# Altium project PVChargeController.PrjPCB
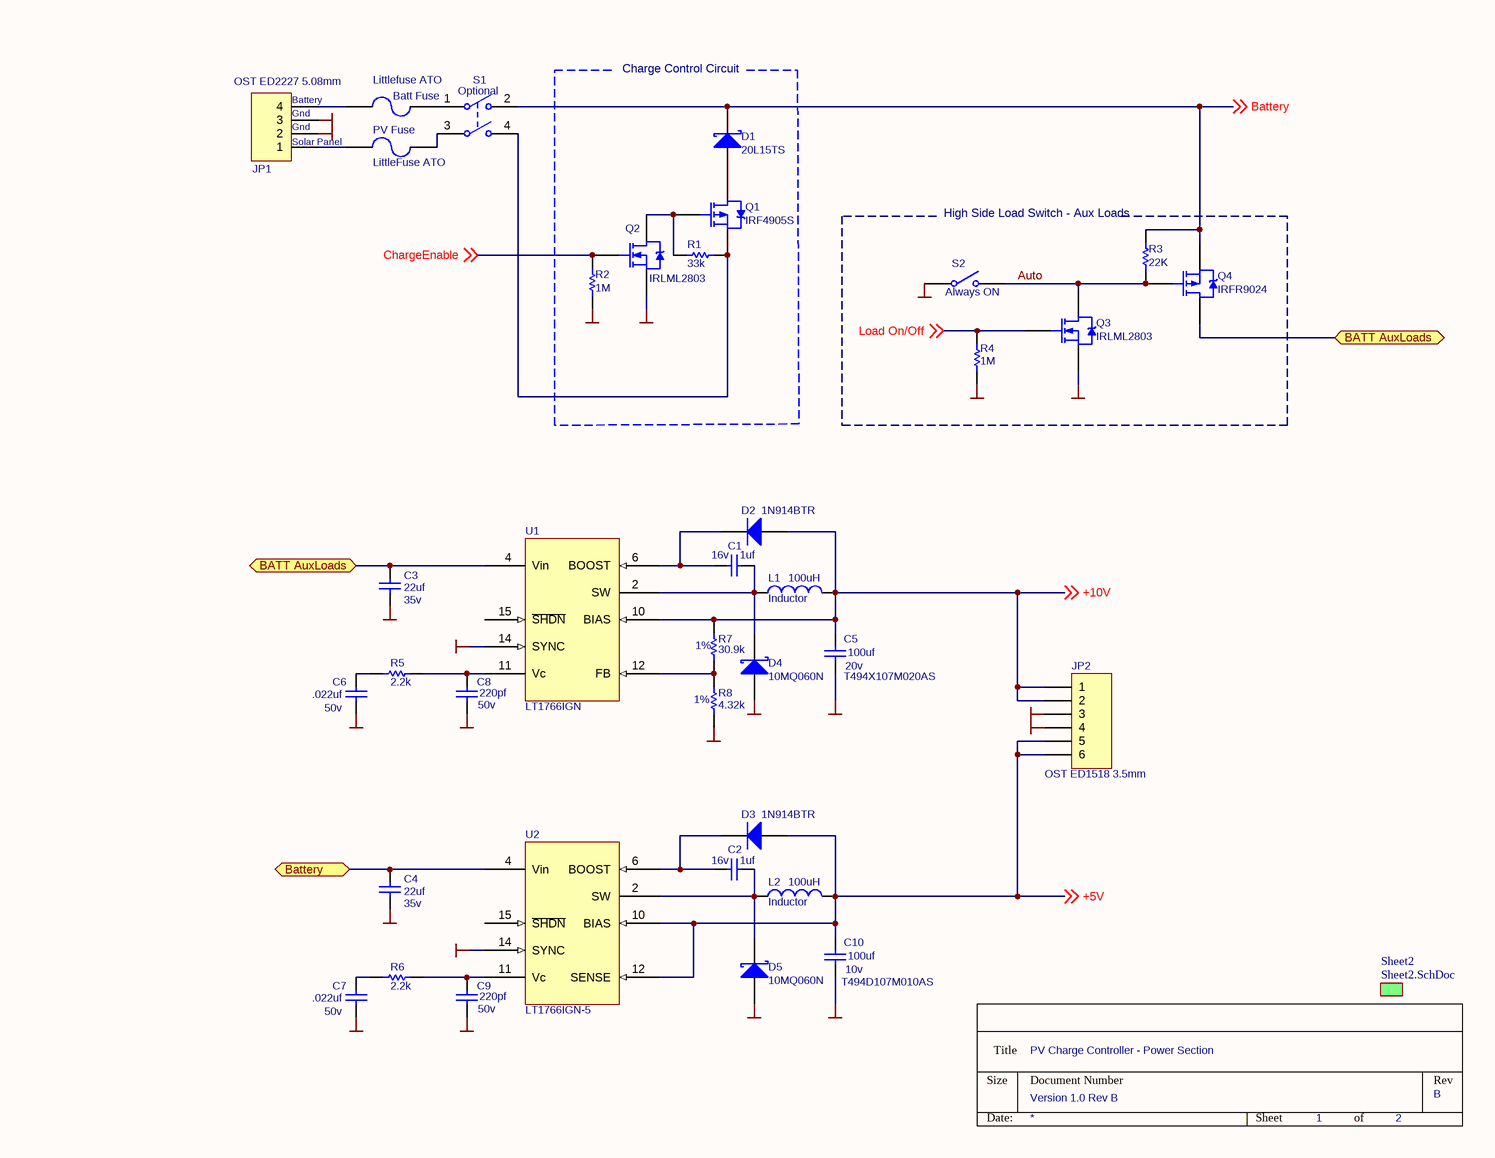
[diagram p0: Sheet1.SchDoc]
2 sheets, 83 parts. Net scope: flat (ports and power ports of the same name join across sheets).
Sheets:
  Sheet1.SchDoc
    Sheet2 = Sheet2.SchDoc

## Sheet Sheet1.SchDoc: PV Charge Controller - Power Section
size Letter; DrawnBy: Richard Dreher; Engineer: Richard Dreher; DocumentNumber: Version 1.0 Rev B; Revision: B; SheetNumber: 1; SheetTotal: 2

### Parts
(Parts that share a designator on the sheet are numbered #1, #2 ... from top to bottom, then left to right.)
?#1  Revision Number: B  Sheet Number: 1  Total Sheets: 2  Sheet Title: PV Charge Controller - Power Section  Document Number: Version 1.0 Rev B  [None Available]  (hidden comment: Title Block Standard)  (graphical)
Batt_Fuse  Littlefuse ATO  [153007]
C1  value 1uf  Voltage: 16v  [C3225-1210]  (hidden comment: ECPU1C105MA5)
C2  value 1uf  Voltage: 16v  [C3225-1210]  (hidden comment: ECPU1C105MA5)
C3  value 22uf  Voltage: 35v  [TC7343-2917]  (hidden comment: T495X226K035AS)
C4  value 22uf  Voltage: 35v  [TC7343-2917]  (hidden comment: T495X226K035AS)
C5  T494X107M020AS  value 100uf  Voltage: 20v  [TC7343-2917]
C6  value .022uf  Voltage: 50v  [C3216-1206]  (hidden comment: ECU-V1H223KBM)
C7  value .022uf  Voltage: 50v  [C3216-1206]  (hidden comment: ECU-V1H223KBM)
C8  value 220pf  Voltage: 50v  [C3216-1206]  (hidden comment: ECU-V1H221KBM)
C9  value 220pf  Voltage: 50v  [C3216-1206]  (hidden comment: ECU-V1H221KBM)
C10  T494D107M010AS  value 100uf  Voltage: 10v  [TC7343-2917]
D1  20L15TS  [SMD-220]
D2  1N914BTR  [DIODE-0.3]
D3  1N914BTR  [DIODE-0.3]
D4  10MQ060N  [DSO-C2/X2.3]
D5  10MQ060N  [DSO-C2/X2.3]
JP1  OST ED2227 5.08mm  [ED2227]
JP2  OST ED1518 3.5mm  [ED1518]
L1  Inductor  value 100uH  [CDRH125]
L2  Inductor  value 100uH  [CDRH125]
PV_Fuse  LittleFuse ATO  [153007]
Q1  IRF4905S  [SMD-220]
Q2  IRLML2803  [SO-G3/Z3.3]
Q3  IRLML2803  [SO-G3/Z3.3]
Q4  IRFR9024  [SIP-G3/E8]
R1  value 33k  [C3216-1206]  (hidden comment: Res1)
R2  value 1M  [C3216-1206]  (hidden comment: Res1)
R3  value 22K  [C3216-1206]  (hidden comment: Res1)
R4  value 1M  [C3216-1206]  (hidden comment: Res1)
R5  value 2.2k  [C3216-1206]  (hidden comment: Res1)
R6  value 2.2k  [C3216-1206]  (hidden comment: Res1)
R7  1%  value 30.9k  [C3216-1206]
R8  1%  value 4.32k  [C3216-1206]
S1  Optional  [HDR2X2]
S2  Always ON  [SPST-2]
U1  LT1766IGN  [SSO-G16]
U2  LT1766IGN-5  [SSO-G16]

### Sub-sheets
Sheet2 = Sheet2.SchDoc: no entries

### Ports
BATT AuxLoads, Battery

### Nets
+5V: C10.2 D3.1(A) JP2.5 JP2.6 L2.2 U2.10(BIAS) U2.12(SENSE) ; off-sheet +5V  [project net Vcc]
Gnd: C3.1 C4.1 C5.1 C6.1 C7.1 C8.1 C9.1 C10.1 D4.1(A) D5.1(A) JP1.2 JP1.3 JP2.3 JP2.4 Q2.2(S) Q3.2(S) R2.1 R4.2 R8.2 S2.1(COMMON) U1.1(GND) U1.8(GND) U1.9(GND) U1.14(SYNC) U1.16(GND) U2.1(GND) U2.8(GND) U2.9(GND) U2.14(SYNC) U2.16(GND)
+10V: C5.2 D2.1(A) JP2.1 JP2.2 L1.2 R7.1 U1.10(BIAS) ; off-sheet +10V
Auto: Q3.3(D) Q4.1(G) R3.2 S2.2(NO)
Battery: D1.2(K) Q4.3(S) R3.1 S1.2(NO1) ; off-sheet Battery
ChargeEnable: Q2.1(G) R2.2 ; off-sheet ChargeEnable
Load On/Off: Q3.1(G) R4.1 ; off-sheet Load On/Off
NetBatt_Fuse_1: Batt_Fuse.1 JP1.4
NetBatt_Fuse_2: Batt_Fuse.2 S1.1(COMMON1)
NetC1_1: C1.1 D4.2(K) L1.1 U1.2(SW)
NetC1_2: C1.2 D2.2(K) U1.6(BOOST)
NetC2_1: C2.1 D5.2(K) L2.1 U2.2(SW)
NetC2_2: C2.2 D3.2(K) U2.6(BOOST)
NetC3_2: C3.2 Q4.4(D) U1.4(Vin) ; port BATT AuxLoads
NetC4_2: C4.2 U2.4(Vin) ; port Battery
NetC6_2: C6.2 R5.1
NetC7_2: C7.2 R6.1
NetC8_2: C8.2 R5.2 U1.11(Vc)
NetC9_2: C9.2 R6.2 U2.11(Vc)
NetD1_3: D1.3(A) Q1.2(D)
NetJP1_1: JP1.1 PV_Fuse.2
NetPV_Fuse_1: PV_Fuse.1 S1.3(COMMON2)
NetQ1_1: Q1.1(G) Q2.3(D) R1.1
NetQ1_3: Q1.3(S) R1.2 S1.4(NO2)
NetR7_2: R7.2 R8.1 U1.12(FB)

Not connected (* = marked no-connect by the designer): U1 15(~{SHDN}); U2 15(~{SHDN})

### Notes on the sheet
- (near JP1) Battery
- Charge Control Circuit
- (near JP1) Solar Panel
- (near JP1) Gnd
- (near R3) High Side Load Switch - Aux Loads

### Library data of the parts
Batt_Fuse PV_Fuse = Fuse 2: Fuse; Manufacturer: Generic Components; Class I: Passive
C1-C10 = Cap: Capacitor; Manufacturer: Generic Components; Class I: Passive
D1 D4 D5 = D Schottky: Schottky Diode; Manufacturer: Generic Components; Class I: Discrete; Class II: Diode - Schottky
D2 D3 = Diode: Default Diode; Manufacturer: Generic Components; Class I: Discrete; Class II: Diode - Switching
JP1 = MHDR1X4: Header, 4-Pin; Manufacturer: Generic Components; Class I: Connector
JP2 = MHDR1X6: Header, 6-Pin; Manufacturer: Generic Components; Class I: Connector
L1 L2 = Inductor: Manufacturer: Generic Components; Class I: Passive
Q1 = IRF4905S: HEXFET Power MOSFET; Manufacturer: International Rectifier; Class I: Discrete; Class II: MOSFET - Power
Q2 Q3 = IRLML2803: HEXFET Power MOSFET; Manufacturer: International Rectifier; Class I: Discrete; Class II: MOSFET - Power
Q4 = IRFR9024: HEXFET Power MOSFET; Manufacturer: International Rectifier; Class I: Discrete; Class II: MOSFET - Power; Note: Pin 2 is trimmed and is electrically connected to Drain.
R1-R8 = Res1: Resistor; Manufacturer: Generic Components; Class I: Passive
S1 = SW-DPST: Double-Pole, Single-Throw Switch; Manufacturer: Generic Components
S2 = SW-SPST: Single-Pole, Single-Throw Switch; Manufacturer: Generic Components
U1 = LT1766IGN: High Voltage 1.5A, 200kHz Step-Down Switching Regulator; Manufacturer: Linear Technologies; CLASS I: Power Management; CLASS II: DC-DC Converter
U2 = LT1766IGN-5: High Voltage 1.5A, 200kHz Step-Down Switching Regulator Fixed 5v Out; Manufacturer: Linear Technologies; CLASS I: Power Management; CLASS II: DC-DC Converter

## Sheet Sheet2.SchDoc: PVCC Control Board  -  Logic Section
size Letter; DrawnBy: RWD; Engineer: RWD; DocumentNumber: Entry F2040; Revision: A; SheetNumber: 2; SheetTotal: 2
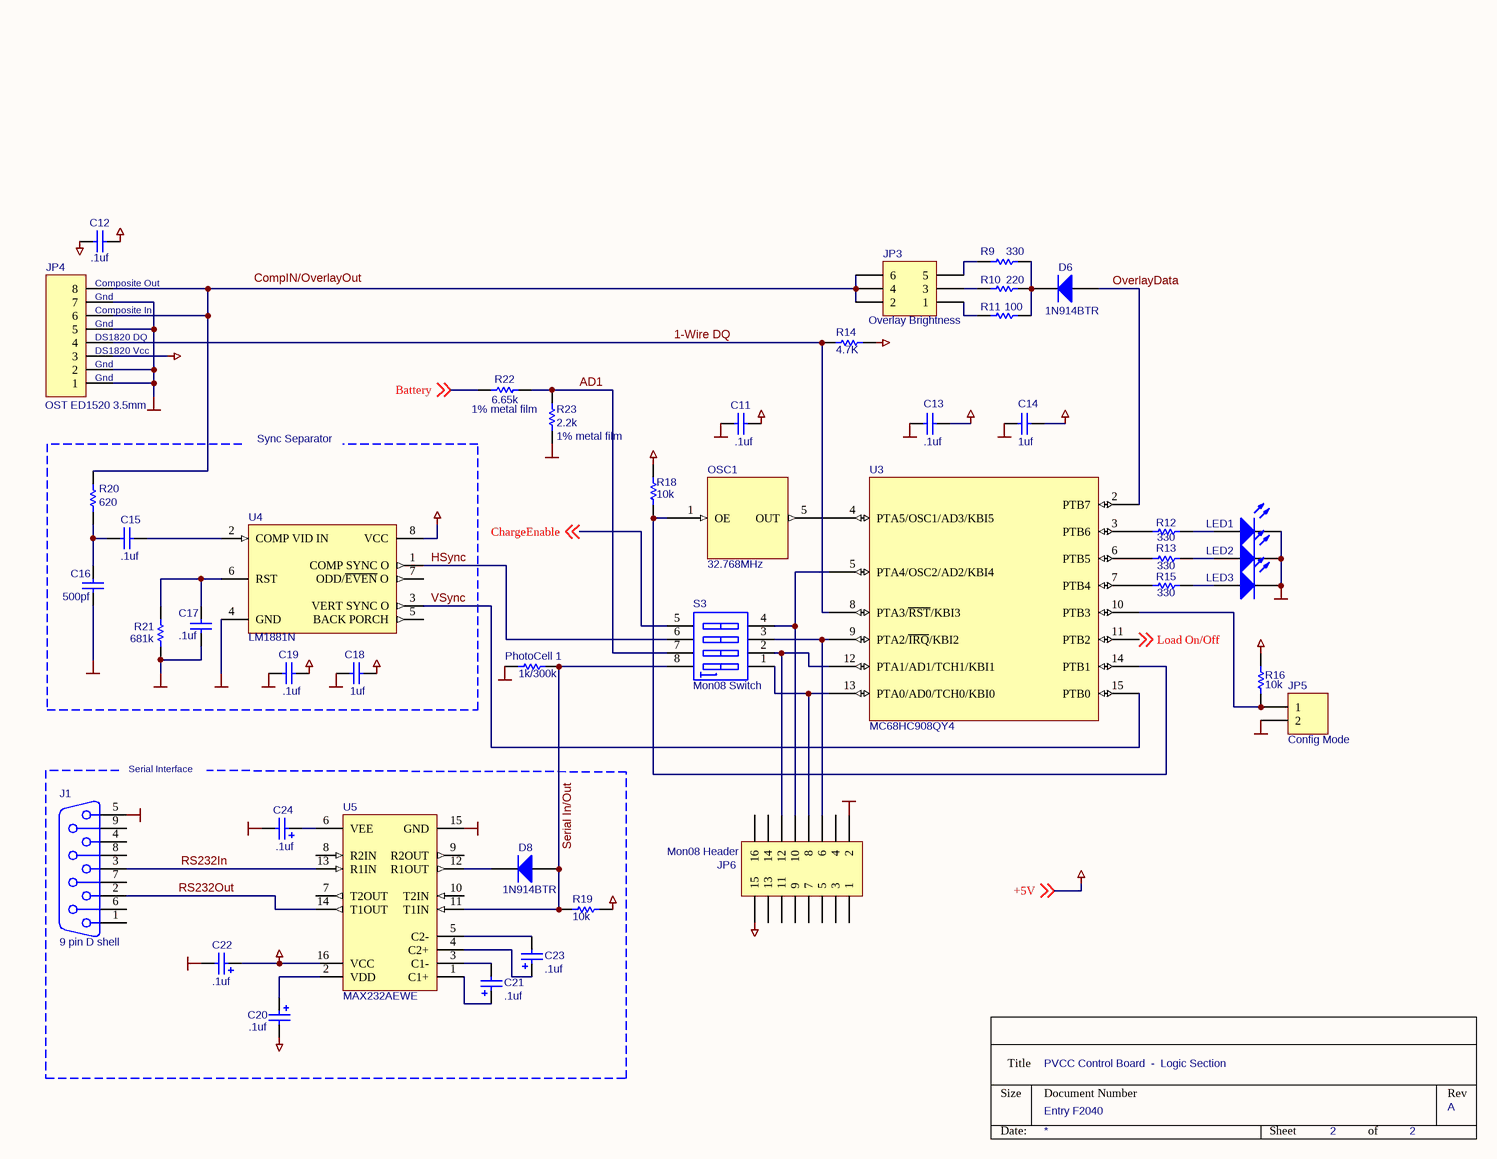
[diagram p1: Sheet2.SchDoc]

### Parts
(Parts that share a designator on the sheet are numbered #1, #2 ... from top to bottom, then left to right.)
?#2  Revision Number: A  Sheet Number: 2  Sheet Title: PVCC Control Board  -  Logic Section  Document Number: Entry F2040  [None Available]  (hidden comment: Title Block Standard)  (graphical)
C11  value .1uf  [R2012-0805]  (hidden comment: Cap)
C12  value .1uf  [R2012-0805]  (hidden comment: Cap)
C13  value .1uf  [R2012-0805]  (hidden comment: Cap)
C14  value 1uf  [R2012-0805]  (hidden comment: Cap)
C15  value .1uf  [R2012-0805]  (hidden comment: Cap)
C16  value 500pf  [C3216-1206]  (hidden comment: Cap)
C17  value .1uf  [R2012-0805]  (hidden comment: Cap)
C18  value 1uf  [R2012-0805]  (hidden comment: Cap)
C19  value .1uf  [R2012-0805]  (hidden comment: Cap)
C20  value .1uf  [R2012-0805]  (hidden comment: Cap Pol3)
C21  value .1uf  [R2012-0805]  (hidden comment: Cap Pol3)
C22  value .1uf  [R2012-0805]  (hidden comment: Cap Pol3)
C23  value .1uf  [R2012-0805]  (hidden comment: Cap Pol3)
C24  value .1uf  [R2012-0805]  (hidden comment: Cap Pol3)
D6  1N914BTR  [DIODE-0.3]
D8  1N914BTR  [DIODE-0.3]
J1  9 pin D shell  [DSUB1.385-2H9]
JP3  Overlay Brightness  [HDR2X3]
JP4  OST ED1520 3.5mm  [ED1520]
JP5  Config Mode  [HDR1X2]
JP6  Mon08 Header  [HDR2X8]
LED1  LED2  [C3216-1206]  (value not drawn)
LED2  LED2  [C3216-1206]  (value not drawn)
LED3  LED2  [C3216-1206]  (value not drawn)
OSC1  32.768MHz  [Osc. 4 Pin]
PhotoCell_1  value 1k/300k  [AXIAL-0.3]
R9  value 330  [C3216-1206]  (hidden comment: Res1)
R10  value 220  [C3216-1206]  (hidden comment: Res1)
R11  value 100  [C3216-1206]  (hidden comment: Res1)
R12  value 330  [C3216-1206]  (hidden comment: Res1)
R13  value 330  [C3216-1206]  (hidden comment: Res1)
R14  value 4.7K  [C3216-1206]  (hidden comment: Res1)
R15  value 330  [C3216-1206]  (hidden comment: Res1)
R16  value 10k  [C3216-1206]  (hidden comment: Res1)
R18  value 10k  [C3216-1206]  (hidden comment: Res1)
R19  value 10k  [C3216-1206]  (hidden comment: Res1)
R20  value 620  [C3216-1206]  (hidden comment: Res1)
R21  value 681k  [C3216-1206]  (hidden comment: Res1)
R22  1% metal film  value 6.65k  [C3216-1206]
R23  1% metal film  value 2.2k  [C3216-1206]
S3  Mon08 Switch  [SO-G8]
U3  MC68HC908QY4  [SO-G16/D10.4]
U4  LM1881N  Class II: Sync Separator  [SO-G8]
U5  MAX232AEWE  [SO-G16/G6.9]

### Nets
Gnd: C11.2 C12.2 C13.2 C14.2 C16.1 C17.1 C18.2 C19.2 C22.2 C24.2 J1.5 JP4.1 JP4.2 JP4.5 JP4.7 JP5.2 JP6.2 LED1.2(K) LED2.2(K) LED3.2(K) OSC1.4(GND) PhotoCell_1.2 R21.1 R23.1 U3.16(Vss) U4.4(GND) U5.15(GND)
Vcc: C11.1 C12.1 C13.1 C14.1 C18.1 C19.1 C20.2 C22.1 JP4.3 JP6.15 OSC1.8(Vdd) R14.1 R16.2 R18.2 R19.2 U3.1(Vdd) U4.8(VCC) U5.16(VCC) ; off-sheet +5V  [also labelled +5V]
1-Wire DQ: JP4.4 R14.2 U3.8(PTA3/~{RST}/KBI3)
AD1: R22.2 R23.2 S3.7(B2)
Battery: R22.1 ; off-sheet Battery
ChargeEnable: S3.5(B4) ; off-sheet ChargeEnable
HSync: S3.6(B3) U4.1(COMP_SYNC_O)
Load On/Off: U3.11(PTB2) ; off-sheet Load On/Off
OverlayData: D6.1(A) U3.2(PTB7)
RS232In: J1.3 U5.13(R1IN)
RS232Out: J1.2 U5.14(T1OUT)
Serial In/Out: D8.1(A) PhotoCell_1.1 R19.1 S3.8(B1) U5.11(T1IN)
VSync: U3.15(PTB0) U4.3(VERT_SYNC_O)
NetC15_1: C15.1 U4.2(COMP_VID_IN)
NetC15_2: C15.2 C16.2 R20.2
NetC17_2: C17.2 R21.2 U4.6(RST)
NetC20_1: C20.1 U5.2(VDD)
NetC21_1: C21.1 U5.1(C1+)
NetC21_2: C21.2 U5.3(C1-)
NetC23_1: C23.1 U5.4(C2+)
NetC23_2: C23.2 U5.5(C2-)
NetC24_1: C24.1 U5.6(VEE)
NetD6_2: D6.2(K) R9.1 R10.1 R11.2
NetD8_2: D8.2(K) U5.12(R1OUT)
NetJP3_1: JP3.1 R11.1
NetJP3_2: JP3.2 JP3.4 JP3.6 JP4.6 JP4.8 R20.1
NetJP3_3: JP3.3 R10.2
NetJP3_5: JP3.5 R9.2
NetJP5_1: JP5.1 R16.1 U3.10(PTB3)
NetJP6_6: JP6.6 S3.3(A3) U3.9(PTA2/~{IRQ}/KBI2)
NetJP6_8: JP6.8 S3.1(A1) U3.13(PTA0/AD0/TCH0/KBI0)
NetJP6_10: JP6.10 S3.4(A4) U3.5(PTA4/OSC2/AD2/KBI4)
NetJP6_12: JP6.12 S3.2(A2) U3.12(PTA1/AD1/TCH1/KBI1)
NetLED1_1: LED1.1(A) R12.2
NetLED2_1: LED2.1(A) R13.2
NetLED3_1: LED3.1(A) R15.2
NetOSC1_1: OSC1.1(OE) R18.1 U3.14(PTB1)
NetOSC1_5: OSC1.5(OUT) U3.4(PTA5/OSC1/AD3/KBI5)
NetR12_1: R12.1 U3.3(PTB6)
NetR13_1: R13.1 U3.6(PTB5)
NetR15_1: R15.1 U3.7(PTB4)

Not connected (* = marked no-connect by the designer): J1 1 4 6 7 8 9 10(MH1) 11(MH2); JP6 1 3 4 5 7 9 11 13 14 16; U4 5(BACK_PORCH) 7(ODD/~{EVEN}_O); U5 7(T2OUT) 8(R2IN) 9(R2OUT) 10(T2IN)

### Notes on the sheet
- (near JP4) Gnd
- (near JP4) Composite Out
- (near JP4) Composite In
- (near JP4) DS1820 DQ
- (near JP4) DS1820 Vcc
- (near J1) Serial Interface
- Labels drawn without touching a wire or pin: CompIN/OverlayOut

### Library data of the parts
C11-C19 = Cap: as C1 on sheet Sheet1
C20-C24 = Cap Pol3: Polarized Capacitor (Surface Mount); Manufacturer: Generic Components; Class I: Passive
D6 D8 = Diode: as D2 on sheet Sheet1
J1 = D Connector 9: Receptacle Assembly, 9 Position, Right Angle; Manufacturer: Generic Components; Package Information: Latest Revision: O; Positions: 9
JP3 = Header 3X2: Header, 3-Pin, Dual row; Manufacturer: Generic Components; Class I: Connector
JP4 = MHDR1X8: Header, 8-Pin; Manufacturer: Generic Components; Class I: Connector
JP5 = Header 2: Header, 2-Pin; Manufacturer: Generic Components; Class I: Connector
JP6 = Header 8X2: Header, 8-Pin, Dual row; Manufacturer: Generic Components; Class I: Connector
LED1-LED3 = LED2: Typical RED, GREEN, YELLOW, AMBER GaAs LED; Manufacturer: Generic Components; Class I: Optoelectronic
OSC1 = SG-531P: Half size DIP high freq. crystal oscillator; Manufacturer: Epson
PhotoCell_1 R9-R16 R18-R23 = Res1: as R1 on sheet Sheet1
S3 = SW DIP-4: DIP Switch; Manufacturer: Generic Components
U3 = MC68HC908QY4CDW: Flash based 8 Bit HC08 Microcontroller; Manufacturer: Motorola; CLASS II: 8 bit
U4 = LM1881N: Video Sync Separator; Manufacturer: National Semiconductor
U5 = MAX232AEWE: +5V Powered, Multi-Channel RS-232 Driver/Receiver; Manufacturer: Maxim; Class I: Communication; Class II: Transceiver

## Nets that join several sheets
Gnd: Sheet1 (30 pins), Sheet2 (27 pins)
Vcc: Sheet1 (7 pins), Sheet2 (18 pins)
Battery: Sheet1 (D1.2 Q4.3 R3.1 S1.2), Sheet2 (R22.1)
ChargeEnable: Sheet1 (Q2.1 R2.2), Sheet2 (S3.5)
Load On/Off: Sheet1 (Q3.1 R4.1), Sheet2 (U3.11)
